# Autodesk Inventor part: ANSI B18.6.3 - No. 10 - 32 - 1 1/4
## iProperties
Comments: To add or edit properties for Autodesk Inventor files, use iProperties.
Created: 2005-01
Part Number: ANSI B18.6.3 - No. 10 - 32 - 1 1/4
Vendor: Autodesk Inc.
Document SubType Name: Modeling
Designer: John Blackburn
Material: Default
Description: Slotted Round Head Machine Screw
Standard: ANSI B18.6.3
Alert: To add or edit properties for Autodesk Inventor files, use iProperties.
Control State: 0
Master: False
Checked Out: False
Shininess: 64.0
Length Units: 11272
Angle Units: 11279
Time Units: 11290
Mass Units: 11286
Length Display Precision: 3
Angle Display Precision: 2
Compacted: True
EGR: 4
Classification: un/spsc 31161501
Density: 0.0
Volumn: 0.0
Area: 0.0
PropertySet Name: Model Information
Author: John Blackburn
Revision Number: 8
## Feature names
1. Body [Revolution]
2. Slot [Extrusion]
3. Chamfer1
